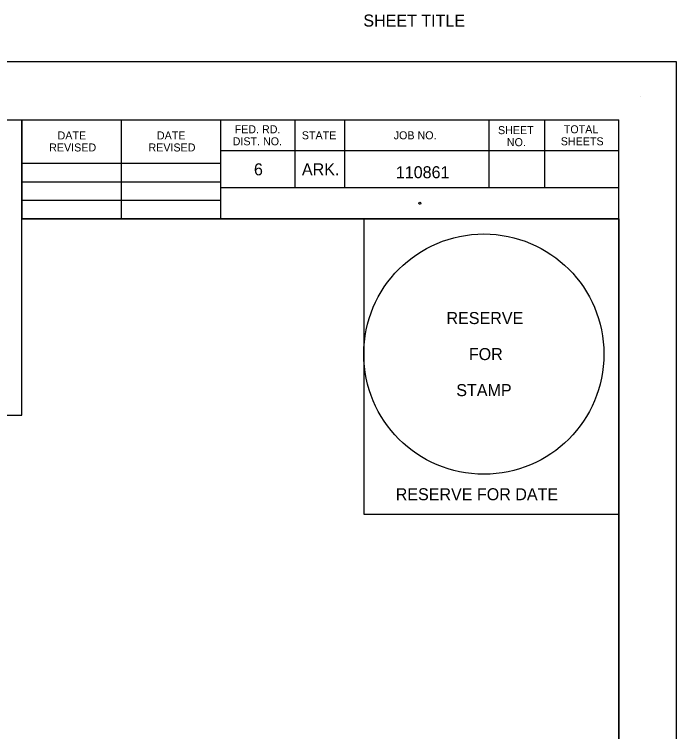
# Model space of a CAD drawing. Extents: x 0 to 19, y -0.6 to 11.2.
# Drawn here: x 13.691 to 17, y 7.655 to 11.238 of the extents above; entities that cross this region are included whole.
import ezdxf

# ---------------------------------------------------------------- set-up
doc = ezdxf.new("R2010")
doc.units = 0
for name, color, linetype in [('G-ANNO-TEXT', 7, 'Continuous'), ('G-Border-Paper', 7, 'Continuous'), ('G-Border-Sheet', 7, 'Continuous'), ('G-No Plot-Anchor', 7, 'Continuous'), ('G-No Plot-Border-1', 7, 'Continuous'), ('G-No Plot-Border-2', 7, 'Continuous'), ('G-No Plot-Stamp-1', 7, 'Continuous'), ('G-Table-Major', 7, 'Continuous'), ('G-Table-Minor', 7, 'Continuous')]:
    doc.layers.add(name, color=color, linetype=linetype)

msp = doc.modelspace()

# ---------------------------------------------------------------- linework, layer by layer
at = {"layer": 'G-ANNO-TEXT'}
msp.add_line((16.821, 10.8269), (16.821, 10.8269), dxfattribs=at)
at = {"layer": 'G-Border-Paper'}
msp.add_lwpolyline([(17, 11), (0, 11), (0, 0), (17, 0)], close=True, dxfattribs=at)
at = {"layer": 'G-Border-Sheet'}
for p in [(0.758, 10.7116), (16.7116, 5.5)]:
    msp.add_line(p, (16.7116, 10.7116), dxfattribs=at)
at = {"layer": 'G-No Plot-Anchor'}
msp.add_circle((15.7161, 10.2941), 0.005, dxfattribs=at)
at = {"layer": 'G-No Plot-Border-1'}
msp.add_lwpolyline([(0.758, 5.5), (0.758, 10.7116), (13.7281, 10.7116), (13.7281, 10.2161), (14.7206, 10.2161), (14.8024, 10.2161), (15.4366, 10.2161), (15.4366, 8.7411), (16.7116, 8.7411), (16.7116, 5.5)], close=True, dxfattribs=at)
at = {"layer": 'G-No Plot-Border-2'}
msp.add_lwpolyline([(0.758, 5.5), (0.758, 10.7116), (12.3781, 10.7116), (12.3781, 9.2366), (13.7281, 9.2366), (13.7281, 10.2161), (14.7206, 10.2161), (14.9256, 10.2161), (16.7116, 10.2161), (16.7116, 5.5)], close=True, dxfattribs=at)
at = {"layer": 'G-No Plot-Stamp-1'}
msp.add_circle((16.0366, 9.5411), 0.6, dxfattribs=at)
at = {"layer": 'G-Table-Major'}
for p, q in [((13.7281, 10.2168), (13.7281, 10.7116)), ((14.7206, 10.7116), (14.7206, 10.2161)), ((13.7281, 10.4946), (14.7206, 10.4946)), ((16.7116, 10.2161), (13.7281, 10.2161))]:
    msp.add_line(p, q, dxfattribs=at)
at = {"layer": 'G-Table-Minor'}
for p, q in [((14.2256, 10.2165), (14.2256, 10.7116)), ((15.0926, 10.7116), (15.0926, 10.3716)), ((15.3411, 10.7116), (15.3411, 10.3716)), ((16.0616, 10.7116), (16.0616, 10.3716)), ((16.3396, 10.7116), (16.3396, 10.3716)), ((16.7116, 10.5561), (14.7206, 10.5561)), ((16.7116, 10.5656), (16.7116, 10.5656)), ((13.7281, 10.4011), (14.7206, 10.4011)), ((16.7116, 10.3716), (14.7206, 10.3716)), ((13.7281, 10.3096), (14.7206, 10.3096))]:
    msp.add_line(p, q, dxfattribs=at)

# ---------------------------------------------------------------- texts
at = {"layer": 'G-ANNO-TEXT'}
for s, height, p in [('SHEET TITLE', 0.06, (15.4345, 11.1771)), ('FED. RD.', 0.04, (14.7913, 10.6439)), ('SHEET', 0.04, (16.1072, 10.6396)), ('TOTAL', 0.04, (16.4361, 10.6439)), ('DATE', 0.04, (13.9066, 10.6131)), ('DATE', 0.04, (14.4029, 10.6131)), ('STATE', 0.04, (15.1271, 10.6139)), ('JOB NO.', 0.04, (15.5861, 10.6139)), ('DIST. NO.', 0.04, (14.7816, 10.5839)), ('NO.', 0.04, (16.1515, 10.5796)), ('SHEETS', 0.04, (16.421, 10.5839)), ('REVISED', 0.04, (13.8646, 10.5531)), ('REVISED', 0.04, (14.3608, 10.5531)), ('6', 0.06, (14.8879, 10.4339)), ('ARK.', 0.06, (15.1276, 10.4339)), ('110861', 0.06, (15.5969, 10.4194))]:
    msp.add_text(s, height=height, dxfattribs=at).set_placement(p)
at = {"layer": 'G-No Plot-Stamp-1'}
for s, p in [('RESERVE', (15.85, 9.6911)), ('FOR ', (15.9617, 9.5111)), ('STAMP', (15.8989, 9.3311)), ('RESERVE FOR DATE', (15.5963, 8.8111))]:
    msp.add_text(s, height=0.06, dxfattribs=at).set_placement(p)

doc.saveas('drawing.dxf')
